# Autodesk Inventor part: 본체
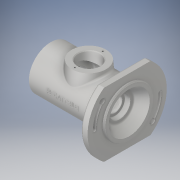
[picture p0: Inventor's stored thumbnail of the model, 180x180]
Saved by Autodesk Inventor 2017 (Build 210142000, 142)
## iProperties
Part Number: 본체
Material: 알루미늄 6061
Document SubType Name: Modeling
Designer: Administrator
Density: 2.7 g/cm^3
Appearance: 알루미늄 - 평지
Mass: 689.243 g
Surface Area: 620.73 cm^2
Volume: 255.275 cm^3
Author: Administrator
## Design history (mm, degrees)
sketch "스케치1"
  geometry: L1 (0, 0)-(102, 0); L2 (0, 0)-(0, 32); L3 (0, 32)-(102, 32); L4 (102, 32)-(102, 0)
  constraints: 8 end point, 2 horizontal, 1 perpendicular, 1 vertical
  dimensions: "d0" = 102 distance of L1.start L1.end; "d1" = 64 diameter of L3 L1
revolve "회전1" sketch "스케치1" stored, may be unused: angle "d2" = 90 deg
sketch "스케치2"
  geometry: L1 (-33.985, 47)-(33.985, 47); L2 (-33.985, -47)-(33.985, -47); A1 r 58 centre (0, 0) between (-33.985, 47) and (-33.985, -47); A2 r 58 centre (0, 0) between (33.985, 47) and (-33.985, 47); A3 r 58 centre (0, 0) between (33.985, -47) and (33.985, 47); A4 r 58 centre (0, 0) between (-33.985, -47) and (33.985, -47); 1 further point
  constraints: 9 point on circle, 4 centre point, 4 end point, 2 horizontal, 1 coincident
  dimensions: "d3" = 116 diameter of A1; "d4" = 94 distance between parallel lines of L2 L1; "d5" = 47 distance from line of point (0, 0) L1
extrude "돌출1" join sketch "스케치2" distance "d6" = 10; taper "d7" = 0 deg
sketch "스케치3"
  geometry: C1 r 36 at (0, 0); 1 further point
  constraints: 1 centre point, 1 coincident
  dimensions: "d8" = 72 diameter of C1
extrude "돌출2" join sketch "스케치3" distance "d9" = 3; taper "d10" = 0 deg
sketch "스케치4"
  geometry: L1 (115, 0)-(8, 0); L2 (8, 0)-(8, 24); L3 (0, -32)-(0, 32) reference; L4 (8, 24)-(11, 24); L5 (11, 24)-(11, 22.5); L6 (11, 22.5)-(22, 22.5); L7 (22, 22.5)-(22, 17.5); L8 (22, 17.5)-(24.25, 17.5); L9 (24.25, 17.5)-(24.25, 18.5); L10 (24.25, 18.5)-(26, 18.5); L11 (26, 18.5)-(26, 17.5); L12 (26, 17.5)-(37, 17.5); L13 (37, 17.5)-(37, 27); L14 (37, 27)-(75, 27); L15 (75, 27)-(75, 17.5); L16 (75, 17.5)-(85.4, 17.5); L17 (86, 16.9)-(86, 15); L18 (86, 15)-(91, 15); L19 (91, 15)-(91, 11); L20 (91, 11)-(93.7, 11); L21 (93.7, 11)-(93.7, 14.5); L22 (101, 15.404)-(101, 20); L23 (101, 20)-(115, 30); L24 (115, -36)-(115, 36) reference; L25 (94.2, 15)-(100.3, 15); L26 (100.3, 15)-(101, 15.404); L27 (115, 30)-(115, 0); A1 r 0.5 centre (94.2, 14.5) between (94.2, 15) and (93.7, 14.5); A2 r 0.6 centre (85.4, 16.9) between (86, 16.9) and (85.4, 17.5); 4 further points
  constraints: 50 end point, 10 perpendicular, 6 horizontal, 5 point on line, 4 point on circle, 4 tangent, 4 vertical, 3 midpoint, 2 centre point, 2 collinear, 2 horizontal alignment
  dimensions: "d11" = 8 distance between parallel lines of L3 L2; "d12" = 48 diameter of L4 L1; "d13" = 3 distance of L2.end L4.end; "d14" = 45 diameter of L6 L1; "d15" = 37 diameter of L10 L1; "d16" = 4 distance between parallel lines of L11 L7; "d17" = 1.75 distance of L9.end L10.end; "d19" = 35 diameter of L12 L1; "d20" = 22 distance between parallel lines of L3 L7; "d21" = 11 horizontal distance of L13.end L10.end; "d22" = 38 distance of L13.end L14.end; "d23" = 54 diameter of L14 L1; "d24" = 30 diameter of L18 L1; "d25" = 22 diameter of L20 L1; "d27" = 40 diameter of L22.end L1; "d28" = 11 distance of L15.end point (86, 17.5); "d29" = 5 distance of L17.end L18.end; "d30" = 14 distance between parallel lines of L22 L24; "d31" = 7.3 distance between parallel lines of L22 L21; "d32" = 30 diameter of L25 L1; "d33" = 0.7 distance from line of L22 L25.end; "d34" = 30 deg angle of L25 L26; "d35" = 0.5 radius of A1 (derived); "d36" = 0.6 radius of A2; "d37" = 60 diameter of L23.end L1
revolve "회전2" sketch "스케치4" stored, may be unused: angle "d38" = 90 deg
node "작업 평면1"
sketch "스케치5"
  geometry: L1 (0, 32)-(0, -32) reference; C1 r 25 at (-56, 0); 1 further point
  constraints: 1 centre point, 1 horizontal alignment
  dimensions: "d40" = 50 diameter of C1; "d41" = 56 distance from line of L1 C1.centre
extrude "돌출3" join sketch "스케치5" stored distance "d42" = 3; taper "d43" = 5 deg
sketch "스케치6"
  geometry: C1 r 25 at (0, 0) reference; C2 r 16 at (0, 0); 1 further point
  constraints: 1 centre point, 1 coincident
  dimensions: "d44" = 32 diameter of C2
extrude "돌출4" cut sketch "스케치6" distance "d45" = 30; taper "d46" = 0 deg
sketch "스케치7"
  geometry: 2 further points
  constraints: 1 coincident
hole "구멍1" sketch "스케치7" at (0, 0) diameter "d47" = 43.376; stored, may be unused: countersink angle "d51" = 90 deg, drill point angle "d53" = 118 deg; dims "d48" = 9, "d49" = 4, "d50" = 2, "d52" = 9
sketch "스케치8"
  geometry: C1 r 16 at (0, 0) reference; A1 r 20.5 centre (0, 0) between (0, 20.5) and (0, -20.5); 1 further point
  constraints: 2 point on circle, 2 vertical alignment, 1 centre point, 1 coincident
  dimensions: "d54" = 41 diameter of A1
hole "구멍2" sketch "스케치8" at (0, 20.5), (0, -20.5) diameter "d55" = 2.459; stored, may be unused: countersink angle "d59" = 90 deg, drill point angle "d61" = 118 deg; dims "d56" = 6, "d57" = 4, "d58" = 2, "d60" = 8
sketch "스케치9" dims "d62" = 96
  geometry: L1 (0, 0)-(-36.77, -30.854); L2 (0, 0)-(-48, 0); A1 r 48 centre (0, 0) between (-48, 0) and (-36.77, -30.854); A2 r 52 centre (0, 0) between (-52, 0) and (-39.834, -33.425); A3 r 44 centre (0, 0) between (-44, 0) and (-33.706, -28.283); A4 r 4 centre (-48, 0) between (-44, 0) and (-52, 0); A5 r 4 centre (-36.77, -30.854) between (-39.834, -33.425) and (-33.706, -28.283); 2 further points
  constraints: 10 point on circle, 5 centre point, 4 end point, 4 tangent, 2 coincident, 1 horizontal, 1 horizontal alignment, 2 other
  dimensions: "d63" = 40 deg angle of L2 L1; "d64" = 8 diameter of A5
extrude "돌출5" cut sketch "스케치9" distance "d65" = 4.4; taper "d66" = 0 deg
sketch "스케치10" dims "d67" = 96
  geometry: L1 (0, 0)-(-36.77, -30.854); L2 (0, 0)-(-48, 0); A1 r 48 centre (0, 0) between (-48, 0) and (-36.77, -30.854); A2 r 50.25 centre (0, 0) between (-50.25, 0) and (-38.494, -32.3); A3 r 45.75 centre (0, 0) between (-45.75, 0) and (-35.047, -29.408); A4 r 2.25 centre (-48, 0) between (-45.75, 0) and (-50.25, 0); A5 r 2.25 centre (-36.77, -30.854) between (-38.494, -32.3) and (-35.047, -29.408); 2 further points
  constraints: 10 point on circle, 5 centre point, 4 end point, 4 tangent, 2 coincident, 1 horizontal, 1 horizontal alignment, 2 other
  dimensions: "d68" = 40 deg angle of L2 L1; "d69" = 4.5 diameter of A5
extrude "돌출6" cut sketch "스케치10" distance "d70" = 10; taper "d71" = 0 deg
sketch "스케치11"
  geometry: C1 r 4 at (-36.77, -30.854); A1 r 4 centre (-36.77, -30.854) between (-39.834, -33.425) and (-33.706, -28.283) reference; 1 further point
  constraints: 1 centre point, 1 coincident
  dimensions: "d72" = 8 diameter of C1
extrude "돌출7" cut sketch "스케치11" distance "d73" = 15; taper "d74" = 0 deg
node "작업 평면2"
sketch "스케치12"
  geometry: L1 (112, -47)-(112, 47) reference; 2 further points
  constraints: 1 horizontal alignment, 1 other
  dimensions: "d79" = 62 distance from line of L1 point (50, 0)
feature "엠보싱1" sketch "스케치12" dims "d80" = 0.5, "d81" = 0
fillet "모깎기1" dims "d82" = 3
fillet "모깎기2" dims "d83" = 3
fillet "모깎기3" dims "d84" = 3
chamfer "모따기1" distance "d85" = 1; stored, may be unused: second distance "d86" = 2, angle "d87" = 45 deg
chamfer "모따기2" distance "d88" = 1; stored, may be unused: second distance "d89" = 2, angle "d90" = 45 deg
node "솔리드1"
pattern_circular "원형 패턴1" dims angle "d76" = 360 deg
other parameters: "d39" = 38
